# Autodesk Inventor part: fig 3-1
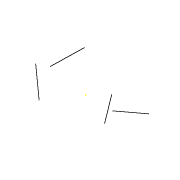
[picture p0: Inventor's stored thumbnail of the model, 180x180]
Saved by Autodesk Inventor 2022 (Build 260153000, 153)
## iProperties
Created: 2011-07
Part Number: fig 3-1
Material: Generic
Document SubType Name: Modeling
Designer: CadCim
Density: 1 g/cm^3
Appearance: Default
Author: CadCim
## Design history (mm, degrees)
sketch "Sketch1"
  geometry: L1 (-24.535, 0.895)-(-9.053, -12.994); L2 (-20.147, 3.302)-(-19.785, 19.15); L3 (5.706, 6.44)-(15.874, -7.118); L4 (12.565, -0.112)-(22.33, 7.212); 1 further point
  constraints: 8 end point, 1 perpendicular, 1 other
